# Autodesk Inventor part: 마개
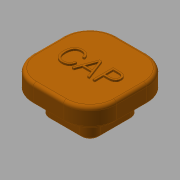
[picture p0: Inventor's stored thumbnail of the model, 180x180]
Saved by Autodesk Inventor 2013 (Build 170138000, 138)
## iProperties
Created: 2018-03
Part Number: 마개
Material: 고무
Document SubType Name: Modeling
Designer: mduedu
Density: 1 g/cm^3
Author: mduedu
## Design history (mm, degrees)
sketch "스케치1"
  geometry: L1 (12.5, 12.5)-(-12.5, 12.5); L2 (-12.5, 12.5)-(-12.5, -12.5); L3 (-12.5, -12.5)-(12.5, -12.5); L4 (12.5, -12.5)-(12.5, 12.5); L5 (12.5, 12.5)-(-12.5, -12.5); L6 (-12.5, 12.5)-(12.5, -12.5); 1 further point
  constraints: 12 end point, 2 midpoint, 2 parallel, 1 horizontal, 1 perpendicular
  dimensions: "d0" = 25 distance of L3.end L2.end; "d1" = 25 distance of L2.end L1.end
extrude "돌출1" new body sketch "스케치1" distance "d2" = 6; taper "d3" = 0 deg
fillet "모깎기1" dims "d4" = 8
fillet "모깎기2" dims "d5" = 1
sketch "스케치2"
  geometry: L1 (4.5, -12.5)-(-4.5, -12.5) reference; L2 (12.5, 4.5)-(12.5, -4.5) reference; L3 (-4.5, 12.5)-(4.5, 12.5) reference; L4 (-12.5, -4.5)-(-12.5, 4.5) reference; L5 (0, -12.5)-(0, 12.5); L6 (-12.5, 0)-(12.5, 0); C1 r 7.5 at (0, 0); A1 r 8 centre (-4.5, -4.5) between (-12.5, -4.5) and (-4.5, -12.5) reference; A2 r 8 centre (4.5, -4.5) between (4.5, -12.5) and (12.5, -4.5) reference; A3 r 8 centre (4.5, 4.5) between (12.5, 4.5) and (4.5, 12.5) reference; A4 r 8 centre (-4.5, 4.5) between (-4.5, 12.5) and (-12.5, 4.5) reference
  constraints: 5 midpoint, 4 end point, 1 centre point
  dimensions: "d21" = 15 diameter of C1
extrude "돌출2" join sketch "스케치2" distance "d7" = 6; taper "d8" = 0 deg
sketch "스케치3"
  geometry: L1 (4.5, 7.5)-(-4.5, 7.5) reference; L2 (-7.5, 4.5)-(-7.5, -4.5) reference; L3 (-4.5, -7.5)-(4.5, -7.5) reference; L4 (7.5, -4.5)-(7.5, 4.5) reference; C1 r 5.5 at (0, 0); A1 r 3 centre (4.5, 4.5) between (7.5, 4.5) and (4.5, 7.5) reference; A2 r 3 centre (-4.5, 4.5) between (-4.5, 7.5) and (-7.5, 4.5) reference; A3 r 3 centre (-4.5, -4.5) between (-7.5, -4.5) and (-4.5, -7.5) reference; A4 r 3 centre (4.5, -4.5) between (4.5, -7.5) and (7.5, -4.5) reference; 2 further points
  constraints: 1 centre point, 1 vertical alignment
  dimensions: "d22" = 2 dimension on C1
extrude "돌출3" cut sketch "스케치3" stored distance "d10" = 10; taper "d11" = 0 deg
fillet "모깎기3" dims "d12" = 1
sketch "스케치4"
  geometry: L1 (4.5, -12.5)-(-4.5, -12.5) reference; L2 (12.5, 4.5)-(12.5, -4.5) reference; L3 (-4.5, 12.5)-(4.5, 12.5) reference; L4 (-12.5, -4.5)-(-12.5, 4.5) reference; L5 (11.5, 4.5)-(11.5, -4.5); L6 (4.5, -11.5)-(-4.5, -11.5); L7 (-11.5, -4.5)-(-11.5, 4.5); L8 (-4.5, 11.5)-(4.5, 11.5); A1 r 8 centre (-4.5, -4.5) between (-12.5, -4.5) and (-4.5, -12.5) reference; A2 r 8 centre (4.5, -4.5) between (4.5, -12.5) and (12.5, -4.5) reference; A3 r 8 centre (4.5, 4.5) between (12.5, 4.5) and (4.5, 12.5) reference; A4 r 8 centre (-4.5, 4.5) between (-4.5, 12.5) and (-12.5, 4.5) reference; A5 r 7 centre (4.5, 4.5) between (11.5, 4.5) and (4.5, 11.5); A6 r 7 centre (4.5, -4.5) between (4.5, -11.5) and (11.5, -4.5); A7 r 7 centre (-4.5, -4.5) between (-11.5, -4.5) and (-4.5, -11.5); A8 r 7 centre (-4.5, 4.5) between (-4.5, 11.5) and (-11.5, 4.5); 1 further point
  constraints: 8 end point, 8 point on circle, 4 centre point, 7 other
  dimensions: "d13" = 1 distance between parallel lines of L8 L3
extrude "돌출4" cut sketch "스케치4" distance "d14" = 1; taper "d15" = 0 deg
chamfer "모따기1" distance "d16" = 0.5; stored, may be unused: second distance "d17" = 2, angle "d18" = 45 deg
sketch "스케치5"
  geometry: 2 further points
  constraints: 1 coincident, 1 other
feature "엠보싱1" sketch "스케치5" dims "d0" = 25, "d1" = 25, "d19" = 0.5, "d20" = 0
fillet "모깎기4" dims "d23" = 0.5
node "솔리드1"
node "투영된 루프1"
node "투영된 루프2"
node "투영된 루프3"
node "참조1"
